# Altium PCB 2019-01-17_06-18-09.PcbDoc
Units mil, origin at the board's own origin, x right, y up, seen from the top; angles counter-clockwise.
Board outline 2440 x 2800 mil, 4 copper layers (Top Layer, MidLayer1, MidLayer2, Bottom Layer); 41 components, 20 nets, 113 pads, 111 vias.
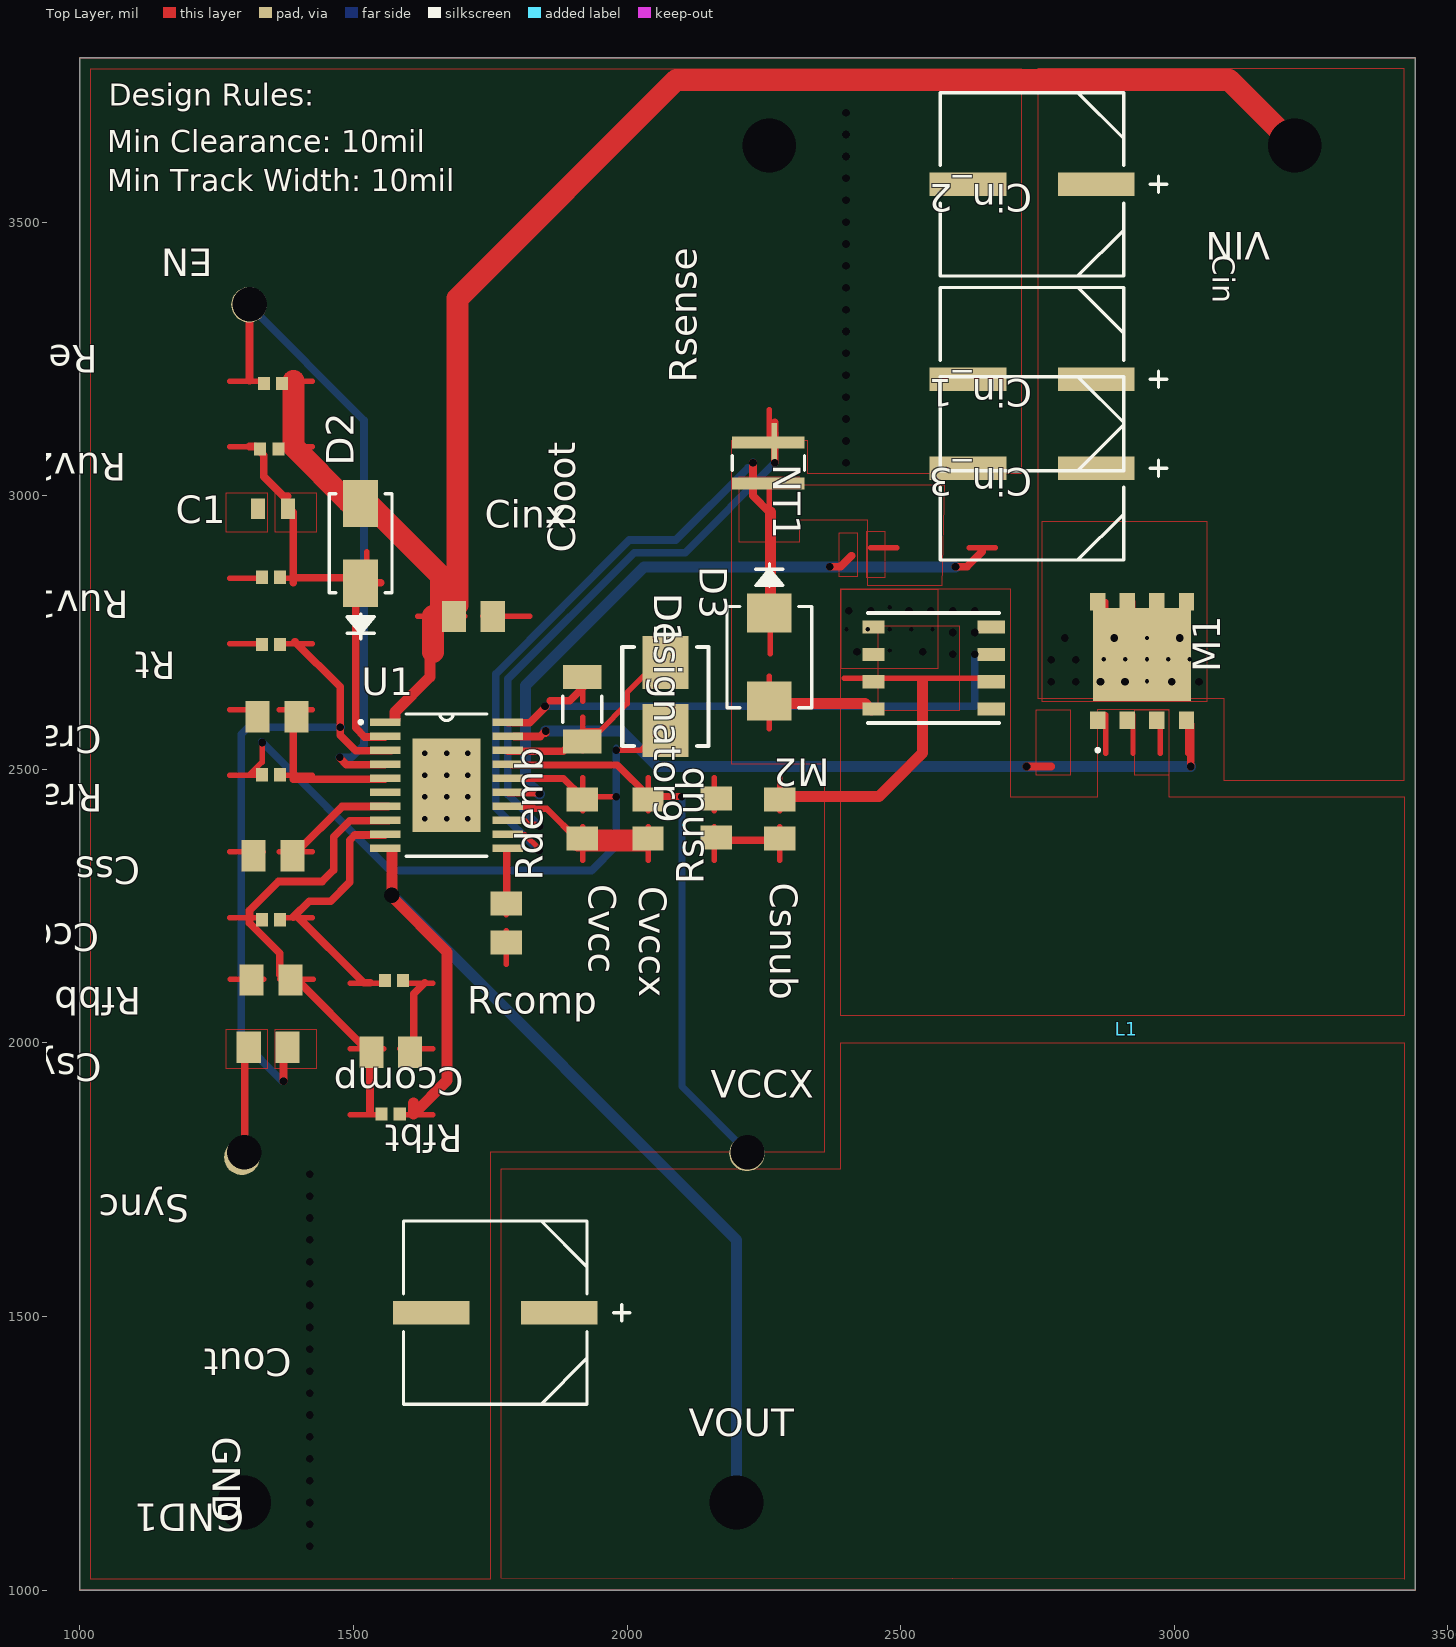
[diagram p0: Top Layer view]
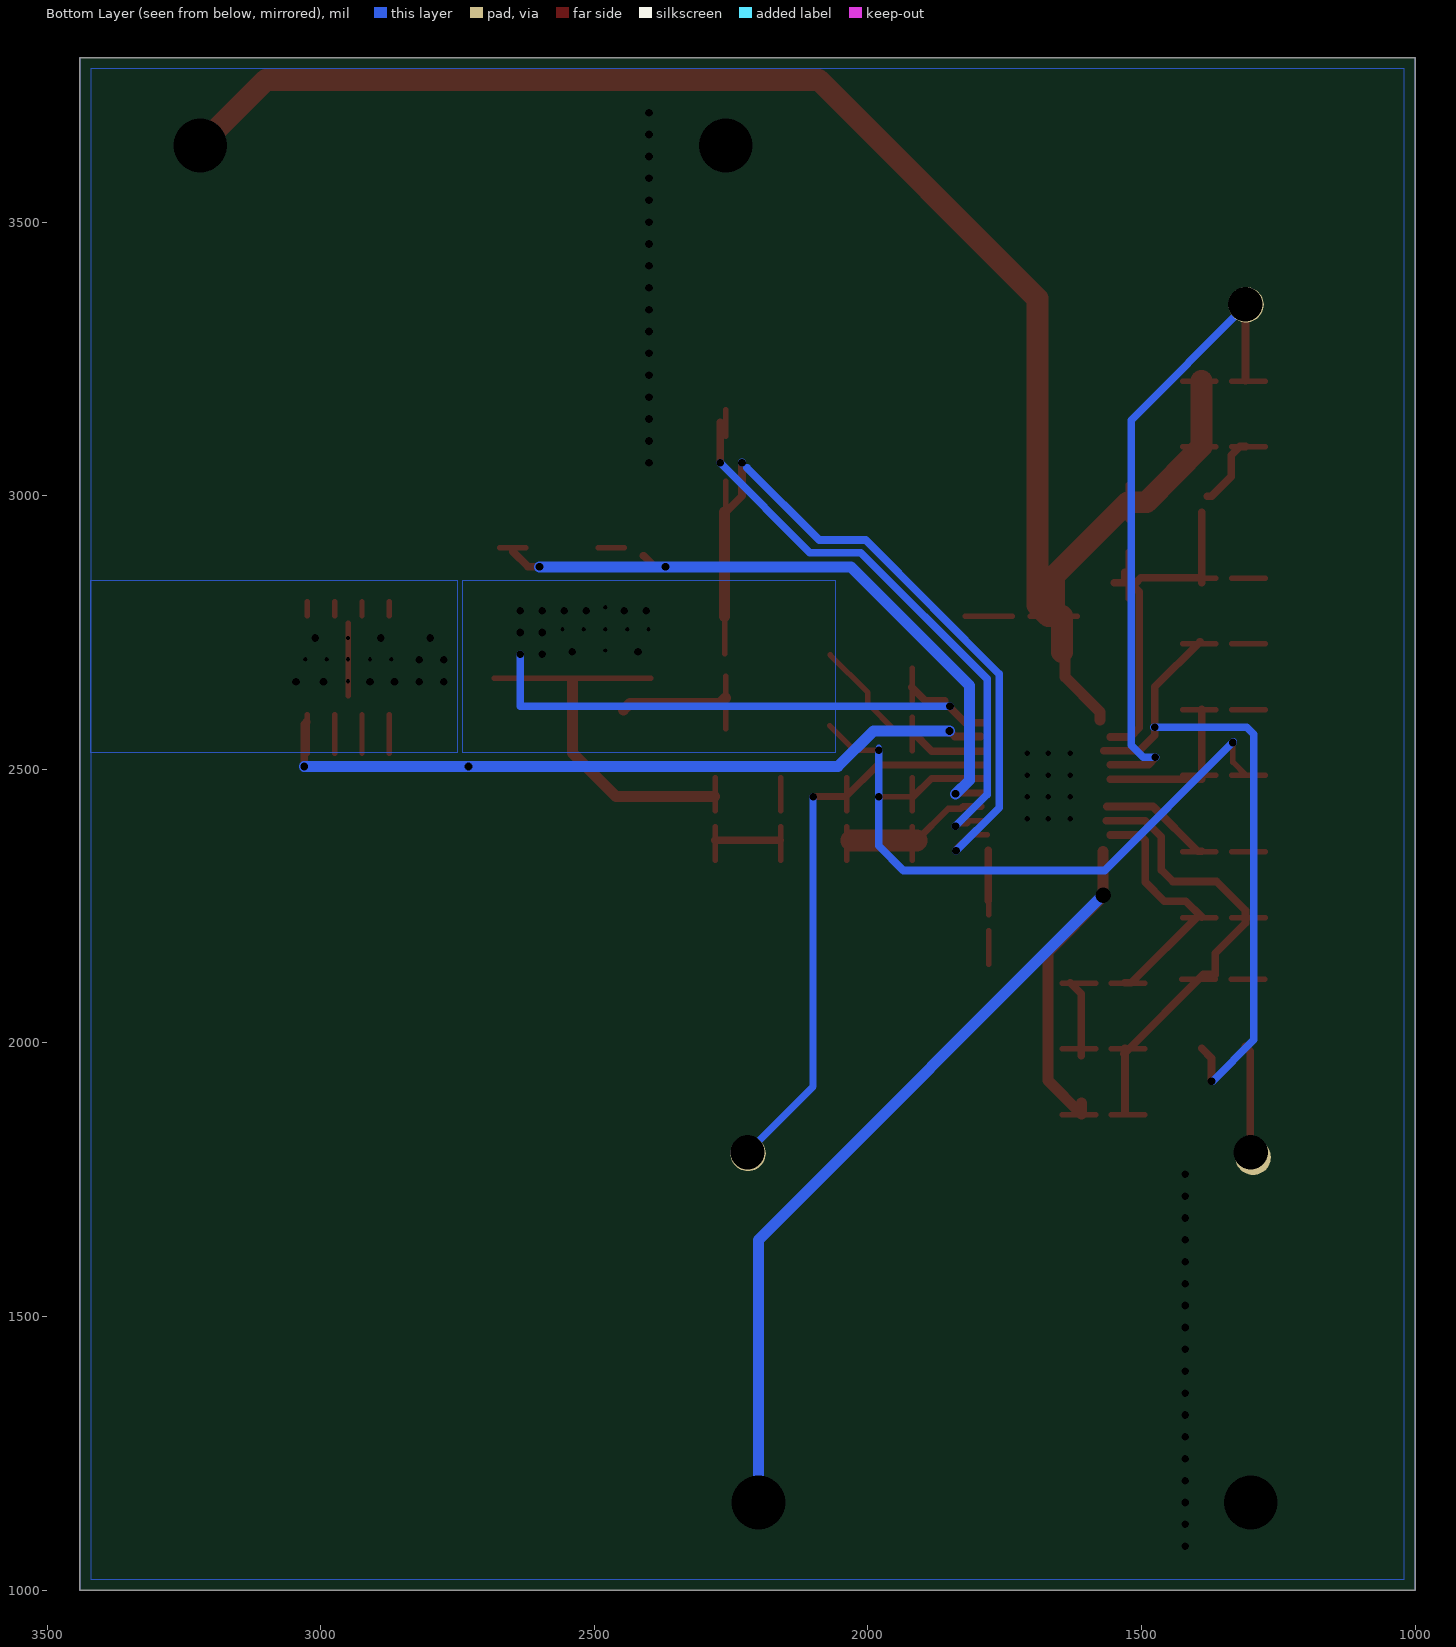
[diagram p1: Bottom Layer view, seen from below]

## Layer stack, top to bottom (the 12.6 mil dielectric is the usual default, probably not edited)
Top Layer: signal copper 1.4
Dielectric: core 12.6, FR-4, Dk 4.8
MidLayer1: signal copper 1.4
Dielectric: prepreg 12.6, FR-4, Dk 4.8
MidLayer2: signal copper 1.4
Dielectric: core 12.6, FR-4, Dk 4.8
Bottom Layer: signal copper 1.4

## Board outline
1000,1000 3440,1000 3440,3800 1000,3800

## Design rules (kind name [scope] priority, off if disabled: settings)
PlaneConnect [All] p0: scope1count=1 scope1_0_kind=Board scope1_0_value=Board scope2count=1 scope2_0_kind=Board scope2_0_value=Board commentlength=0 planeconnectstyle=Direct reliefexpansion=20 reliefentries=4 reliefconductorwidth=10 reliefairgap=10
PlaneConnect [All] p1: planeconnectstyle=Direct reliefexpansion=20 reliefentries=4 reliefconductorwidth=10 reliefairgap=10
PolygonConnect [All] p0: scope1count=1 scope1_0_kind=Board scope1_0_value=Board scope2count=1 scope2_0_kind=Board scope2_0_value=Board commentlength=0 connectstyle=Direct reliefconductorwidth=10 reliefentries=4 polygonreliefangle="90 Angle"
PolygonConnect [All] p1: connectstyle=Direct reliefconductorwidth=10 reliefentries=4 polygonreliefangle="90 Angle"

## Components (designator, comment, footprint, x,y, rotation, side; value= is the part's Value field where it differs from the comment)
C1 "" 0603 1353,2976 r0 top
Cboot "" 1206 1918,2610 r90 top
Ccomp "" 0805 1568,1983 r180 top
Ccomp2 "" 0402 1349,2225 r180 top
Cin_1 "" CAPSMT_62_E12 2740,3213 r180 top
Cin_2 "" CAPSMT_62_E12 2740,3569 r180 top
Cin_3 "" CAPSMT_62_E12 2740,3050 r180 top
Cinx "" 0805 1719,2779 r0 top
Cout "" CAPSMT_62_E12 1759,1507 r180 top
Cramp "" 0805 1360,2596 r180 top
Csnub "" 0805 2279,2409 r270 top
Css "" 0805 1353,2342 r180 top
Csync "" 0805 1344,1992 r180 top
Cvcc "" 0805 1918,2409 r270 top
Cvccx "" 0805 2038,2409 r270 top
D1 "" DO-214BA 2070,2633 r270 top
D2 "" SMA 1513,2913 r90 top
D3 "" SMB 2260,2705 r270 top
EN "" TP-1502 1309,3349 r180 top
GND "" TP-1502 2258,3638 r270 top
GND1 "" TP-1502 1300,1158 r180 top
L1 "" SER2918H 2913,2025 r270 top
M1 "" TRANS_NexFET_Q5A 2941,2698 r90 top
M2 "" PowerDFN56 2560,2685 r180 top
NT1 "" NET_TIED 2269,3099 r270 top
Rcomp "" 0402 1574,2114 r0 top
Rdemb "" 0805 1779,2219 r90 top
Renable "" 0402 1353,3205 r180 top
Rfbb "" 0805 1349,2115 r180 top
Rfbt "" 0402 1568,1870 r180 top
Rramp "" 0402 1349,2490 r180 top
Rsense "" 0612 2258,3060 r90 top
Rsnub "" 0805 2163,2411 r90 top
Rt "" 0402 1349,2728 r180 top
Ruv1 "" 0402 1349,2851 r180 top
Ruv2 "" 0402 1346,3085 r180 top
Sync "" TP-1502 1296,1791 r180 top
U1 "" MXA20A 1670,2471 r0 top
VCCX "" TP-1502 2219,1798 r0 top
VIN "" TP-1502 3219,3638 r180 top
VOUT "" TP-1502 2198,1159 r0 top

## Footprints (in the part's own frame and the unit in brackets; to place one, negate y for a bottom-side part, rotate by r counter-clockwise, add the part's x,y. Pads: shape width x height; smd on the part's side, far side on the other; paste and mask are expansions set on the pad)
0402 [mil]
  rect 22x24 smd: 1(-16.5,0) 2(16.5,0)
0603 [mil]
  rect 26x38 smd: 1(-27.5,0) 2(27.5,0)
0612 [mil]
  rect 22x132 smd: 1(-37.5,0) 2(37.5,0)
  silkscreen extent -13,-66 13,66
0805 [mil]
  rect 44x57 smd: 1(-35.5,0) 2(35.5,0)
1206 [mil]
  rect 44x71 smd: 1(-59,0) 2(59,0)
  silkscreen extent -24,-36 24,36
CAPSMT_62_E12 [mil]
  rect 140x43 smd: 1(-117,0) 2(117,0)
  silkscreen extent -246,-168 168,168
DO-214BA [mm]
  rect 2.45x2.15 smd: 1(-1.575,0) 2(1.575,0)
  silkscreen extent -2.3,-2 2.3,2
MXA20A [mil]
  rect 56x14 smd: 1(-112,115.16) 2(-112,89.57) 3(-112,63.98) 4(-112,38.39) 5(-112,12.8) 6(-112,-12.8) 7(-112,-38.39) 8(-112,-63.98) 9(-112,-89.57) 10(-112,-115.16) 11(112,-115.16) 12(112,-89.57) 13(112,-63.98) 14(112,-38.39) 15(112,-12.8) 16(112,12.8) 17(112,38.39) 18(112,63.98) 19(112,89.57) 20(112,115.16)
  rect 124x171 smd: 21(0,0)
  silkscreen extent -160,-130 74,130
NET_TIED [mil]
  rect 38x10 smd: 1(-15,0) 2(15,0)
PowerDFN56 [mm]
  rect 1.27x0.61 smd: 1(-2.67,1.905) 1(-2.67,1.905) 2(-2.67,0.635) 2(-2.67,0.635) 3(-2.67,-0.635) 3(-2.67,-0.635) 4(-2.67,-1.905) 4(-2.67,-1.905)
  rect 1.02x0.61 smd: 5(2.795,-1.905) 5(2.795,-1.905) 6(2.795,-0.635) 6(2.795,-0.635) 7(2.795,0.635) 7(2.795,0.635) 8(2.795,1.905) 8(2.795,1.905)
  silkscreen extent -3.05,-2.55 3.05,2.55
SER2918H [mil]
SMA [mil]
  rect 86x64 smd: 1(-73,0) 2(73,0)
  silkscreen extent -174,-58 90,58
SMB [mil]
  rect 71x81 smd: 1(-80.5,0) 2(80.5,0)
  silkscreen extent -171,-78 93,78
TP-1502 [mil]
  round 65 / inner round 0 / far side round 65 hole 32: 1(0,0)
TRANS_NexFET_Q5A [mm]
  rect 0.8x0.7 smd: 1(-2.752,2.055) 2(-2.752,0.685) 3(-2.752,-0.685) 4(-2.752,-2.055) 5(2.752,-2.055) 6(2.752,-0.685) 7(2.752,0.685) 8(2.752,2.055)
  rect 4.3x4.56 smd: 9(0.3,0)
  silkscreen extent -4.22,1.98 -4.07,2.13

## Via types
v1: diameter 0, hole 14, Top Layer to Bottom Layer, 76 vias
v2: diameter 0, hole 8, Top Layer to Bottom Layer, 14 vias
v3: diameter 0, hole 10, Top Layer to Bottom Layer, 12 vias
v4: diameter 0, hole 98, Top Layer to Bottom Layer, 4 vias
v5: diameter 0, hole 63, Top Layer to Bottom Layer, 3 vias
v6: diameter 0, hole 28, Top Layer to Bottom Layer, 2 vias

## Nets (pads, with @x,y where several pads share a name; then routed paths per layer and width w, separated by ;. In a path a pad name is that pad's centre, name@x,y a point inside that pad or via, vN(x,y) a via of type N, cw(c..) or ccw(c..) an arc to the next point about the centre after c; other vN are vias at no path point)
0: Cinx.2 Cout.2 Cramp.2 Css.2 Cvcc.2 Cvccx.2 NT1.1 NT1.2 Rdemb.2 Rfbb.2 Rsense.2 Rsnub.2 Rt.2 Ruv1.2 U1.6 U1.11 U1.13 U1.14 U1.21 | length 1218.4
  Top Layer w10: Rdemb.2@1779,2234 1779,2295 ; U1.13@1788,2406 1814,2406 1819,2400 1832,2400
  Top Layer w14: Rdemb.2@1780,2260 U1.11@1780,2352 ; v1(2270,3060) 2270,3134
  Bottom Layer w14: v1(1840,2396) 1782,2454 1782,2665 2013,2896 2106,2896 v1(2270,3060)
1: Cin_1.1 Cin_2.1 Cin_3.1 Cinx.1 D2.2 M1.5 M1.6 M1.7 M1.8 M1.9 Renable.1 Ruv2.1 U1.1 VIN.1 | length 3700.5
  Top Layer w10: Ruv2.1@1364,3089 1425,3089 ; Renable.1@1364,3209 1425,3209 ; D2.2@1524,2956 D2.2@1524,3020 ; 1617,2779.5 Cinx.1@1703,2779.5 ; M1.9@2874.5,2781 2874.5,2806 ; M1.9@2924.5,2781 M1.7@2924.5,2806 ; M1.9@2949.5,2634 M1.9@2949.5,2767 ; M1.9@2974.5,2781 M1.6@2974.5,2806 ; M1.9@3024.5,2781 M1.5@3024.5,2806
  Top Layer w20: 1391,3093 1393,3091 1393,3078 ; D2.2@1482,2988 1525,2988 D2.2@1530,2988 ; U1.1@1576,2590 1576,2605 1640,2669 1640,2709
  Top Layer w40: 1390,3210 1390,3090 1491,2988 1525,2988 1660,2853 1660,2780 ; 1645,2714 1645,2780 1670,2780 1690,2800 1690,3360 2090,3760 3100,3760 v4(3220,3640)
  other v1: 2775,2660 2820,2660 2865,2660 2910,2660 2995,2660 3045,2660 2775,2700 2820,2700 2800,2740 2890,2740 3010,2740
  other v2: 2950,2661 2871,2701 2910,2701 2950,2701 2989,2701 3028,2701 2950,2740
2: Css.1 U1.7 | length 268
  Top Layer w10: 1364,2349 1425,2349
  Top Layer w14: Css.1@1390,2350 1397,2350 1479,2432 U1.7@1563,2432
3: M2.4 U1.15 | length 1297.8
  Top Layer w10: 2625,2905 2673,2905
  Top Layer w13: U1.15@1782,2457 1837,2457
  Top Layer w14: v1(2370,2870) 2390,2870 2410,2890 ; v1(2600,2870) 2621,2870 2649,2898
  Bottom Layer w14: 1839,2455 v1(1840,2455)
  Bottom Layer w20: v1(1840,2455) 1814,2480 1814,2653 2031,2870 v1(2600,2870)
4: C1.2 D2.1 Ruv1.1 Ruv2.2 U1.2 | length 986.4
  Top Layer w10: 1274,3089 Ruv2.2@1335,3089 ; Ruv1.1@1364,2849 1425,2849 ; D2.1@1524,2812 1524,2898
  Top Layer w14: 1310,3090 1320,3090 1336,3074 1336,3035 1372,2999 1380,2999 ; 1390,2841 1390,2850 ; C1.2@1390,2970 1390,2850 ; D2.1@1530,2860 1530,2850 1504,2824 1504,2576 1520,2559 U1.2@1557,2559 ; 1550,2841 1510,2841 1501,2850 1390,2850
5: Csync.1 Rt.1 U1.3 | length 1288.9
  Top Layer w10: Rt.1@1364,2729 1425,2729
  Top Layer w14: v1(1372,1930) 1372,1972 Csync.1@1390,1990 ; 1393,2733 1476,2651 1476,2562 1504,2534 ; 1505,2534 U1.3@1569,2534
  Bottom Layer w14: 1295,2563 1295,2006 1370,1930 ; 1295,2564 1308,2577 1477,2577
  other v1: 1476,2577
6: Cramp.1 Rramp.2 U1.5 | length 417
  Top Layer w10: 1364,2489 1425,2489 ; 1364,2609 1425,2609
  Top Layer w14: Cramp.1@1390,2610 1390,2482 U1.5@1557,2482
7: EN.1 Renable.2 U1.4 | length 1227.4
  Top Layer w10: 1274,3209 Renable.2@1335,3209
  Top Layer w14: 1310,3210 EN.1@1310,3345 ; 1475,2521 1487,2508 U1.4@1557,2508
  Bottom Layer w14: EN.1@1310,3347 1519,3138 1519,2544 1497,2522 1474,2522
  other v1: 1475,2522
  other v5: 1310,3350
9: Ccomp2.1 Ccomp.1 U1.9 | length 583
  Top Layer w10: Ccomp2.1@1364,2229 1425,2229 ; 1494,2109 1555,2109
  Top Layer w14: 1390,2230 1419,2259 1458,2259 1493,2294 1493,2370 1502,2380 U1.9@1557,2380 ; 1394,2234 1519,2110 1530,2110
10: Ccomp2.2 Rcomp.2 Rfbb.1 Rfbt.2 U1.8 | length 1348.8
  Top Layer w10: 1274,2229 Ccomp2.2@1335,2229 ; Rfbb.1@1365,2116 1426,2116 ; 1494,1869 Rfbt.2@1555,1869 ; 1494,1989 1555,1989 ; 1584,1989 1645,1989 ; Rcomp.2@1584,2109 1645,2109
  Top Layer w14: 1530,1873 1530,1982 ; 1530,1990 1530,1982 ; 1532,1980 1530,1982 ; U1.8@1564,2406 1493,2406 1464,2377 1464,2316 1443,2295 1363,2295 1310,2242 1310,2230 1310,2219 1365,2164 1365,2125 1387,2125 1530,1982 ; 1610,1977 1610,1990 1610,2090 1630,2110
11: C1.1 Cin_1.2 Cin_2.2 Cin_3.2 Cout.1 Rfbt.1 U1.10 VOUT.1 | length 2954.7
  Top Layer w10: 1274,2349 1335,2349 ; 1274,2609 1335,2609 ; 1274,2729 1335,2729 ; 1274,2849 1335,2849 ; 1275,2116 1336,2116 ; Rfbt.1@1584,1869 1645,1869 ; 1736,2779.5 1822,2779.5 ; 1779,2144 1779,2205 ; 1919,2334 1919,2395 ; 2039,2334 2039,2395 ; 2159,2424 2159,2485 ; 2260,3109 2260,3157
  Top Layer w12: 1793,2432 1826,2432 1830,2428 1853,2428 1911,2370
  Top Layer w20: U1.10@1570,2350 v6(1570,2270) 1570,2267 1671,2166 1671,1931 1610,1870 1610,1890
  Top Layer w40: 1911,2370 2030,2370
  Bottom Layer w20: v6(1570,2270) 2200,1640 VOUT.1@2200,1150
  other v1: 1420,1080 1420,1120 1420,1160 1420,1200 1420,1240 1420,1280 1420,1320 1420,1360 1420,1400 1420,1440 1420,1480 1420,1520 1420,1560 1420,1600 1420,1640 1420,1680 1420,1720 1420,1760 2400,3060 2400,3100 2400,3140 2400,3180 2400,3220 2400,3260 2400,3300 2400,3340 2400,3380 2400,3420 2400,3460 2400,3500 2400,3540 2400,3580 2400,3620 2400,3660 2400,3700
  other v3: 1630,2410 1670,2410 1709,2410 1630,2450 1670,2450 1709,2450 1630,2489 1670,2489 1709,2489 1630,2529 1670,2529 1709,2529
  other v4: 1300,1160 2200,1160 2260,3640
  other v6: 2200,1160
13: D3.1 M2.1 M2.2 M2.3 Rsense.1 U1.12 | length 1628.7
  Top Layer w10: U1.12@1782,2380 1813,2380 1839,2355 v1(1839,2351) ; 2260,2920 Rsense.1@2260,3026 ; 2261.5,2711 2261.5,2847 ; 2445,2905 2493,2905
  Top Layer w14: v1(2230,3060) 2230,3000 2260,2970
  Top Layer w20: D3.1@2262,2779 2262,2970
  Bottom Layer w14: v1(1839,2351) 1760,2430 1760,2674 2004,2919 2089,2919 2221,3051 ; v1(2230,3060) 2230,3061
14: M1.4 U1.19 | length 1463.1
  Top Layer w10: 3024.5,2529 M1.4@3024.5,2600
  Top Layer w14: U1.19@1794,2560 1841,2560 v1(1851,2570) ; 1851,2566 1851,2568 ; v1(2730,2505) 2775,2505 ; M1.4@3026,2586 M1.4@3026,2587 ; v1(3030,2505) M1.4@3030,2582
  Bottom Layer w20: v1(1851,2570) 1990,2570 2055,2505 v1(2730,2505) v1(3030,2505)
15: Cboot.1 D1.1 GND1.1 GND.1 Rdemb.1 U1.18 | length 432.6
  Top Layer w10: Cboot.1@1919,2534 1919,2595 ; Cboot.1@1920,2570 1950,2570 2000,2620 2000,2640 D1.1@2069,2709
  Top Layer w14: U1.18@1782,2533 1883,2533 Cboot.1@1920,2570
16: Cvcc.1 D1.2 Rramp.1 U1.16 | length 1459.8
  Top Layer w10: 1274,2489 1335,2489 ; 1310,2490 1333,2513 v1(1333,2549) ; Cvcc.1@1917,2450 1920,2450 v1(1980,2450) ; Cvcc.1@1919,2424 1919,2485 ; 1985,2535 v1(1980,2535) 2025,2535 D1.2@2070,2580
  Top Layer w13: U1.16@1782,2483 1884,2483 Cvcc.1@1917,2450
  Bottom Layer w10: v1(1980,2535) 1980,2540
  Bottom Layer w14: 1332,2550 v1(1333,2549) 1567,2315 1935,2315 1980,2360 v1(1980,2450) v1(1980,2535)
17: Cboot.2 Csnub.1 D3.2 M1.1 M1.2 M1.3 M2.5 M2.6 M2.7 M2.8 U1.20 | length 2366.6
  Top Layer w10: 1919,2624 Cboot.2@1919,2685 ; 2259.5,2574 2259.5,2670 ; Csnub.1@2279,2424 2279,2485 ; 2397,2666 2683,2666 ; 2874.5,2529 2874.5,2600 ; 2924.5,2529 M1.2@2924.5,2600 ; 2974.5,2529 M1.3@2974.5,2600
  Top Layer w14: U1.20@1782,2585 1822,2585 1851,2614 ; 1860,2625 1895,2625 Cboot.2@1920,2650
  Top Layer w20: D3.2@2260,2630 2270,2620 2435,2620 M2.8@2447,2608 ; Csnub.1@2280,2450 2460,2450 2540,2530 2540,2659
  Bottom Layer w14: v1(1850,2615) 2635,2615 v1(2635,2710)
  other v1: 2595,2710 2420,2715 2540,2715 2595,2750 2635,2750 2405,2790 2445,2790 2515,2790 2555,2790 2595,2790 2635,2790
  other v2: 2480,2717 2401,2756 2440,2756 2480,2756 2519,2756 2558,2756 2480,2796
18: Ccomp.2 Rcomp.1
29: Csnub.2 Rsnub.1 | length 242
  Top Layer w10: 2159,2334 Rsnub.1@2159,2395 ; 2279,2334 Csnub.2@2279,2395
  Top Layer w14: Rsnub.1@2160,2370 Csnub.2@2280,2370
35: Cvccx.1 U1.17 VCCX.1 | length 1096.7
  Top Layer w10: Cvccx.1@2039,2424 2039,2485
  Top Layer w13: U1.17@1788,2508 1982,2508 2040,2450 v1(2100,2450)
  Bottom Layer w13: v1(2100,2450) 2100,1920 v5(2220,1800)
38: Csync.2 Sync.1 | length 197.7
  Top Layer w14: Sync.1@1301,1800 1301,1985 Csync.2@1310,1994
  other v5: 1300,1800

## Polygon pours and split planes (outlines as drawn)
38 on Top Layer " " (solid, pour order 0): 1267,1953 1267,2025 1342,2025 1342,1953
5 on Top Layer " " (solid, pour order 1): 1357,1953 1357,2025 1432,2025 1432,1953
4 on Top Layer " " (solid, pour order 2): 1357,2933 1357,3005 1432,3005 1432,2933
11 on Top Layer " " (solid, pour order 3): 1267,2933 1267,3005 1342,3005 1342,2933
1 on Top Layer " " (solid, pour order 4): 2759,2623 2759,2953 3059,2953 3059,2623
17 on Top Layer " " (solid, pour order 5): 2928,2489 2928,2609 2990,2609 2990,2489
14 on Top Layer " " (solid, pour order 6): 2748,2489 2748,2609 2810,2609 2810,2489
3 on Top Layer " " (solid, pour order 7): 2388,2852 2388,2932 2421,2932 2421,2852
13 on Top Layer " " (solid, pour order 8): 2438,2850 2438,2935 2471,2935 2471,2850
17 on Top Layer " " (solid, pour order 9): 2391,2684 2391,2829 2568,2829 2568,2684
11 on Top Layer " " (solid, pour order 16): 1770,1022 1770,1770 2390,1770 2390,2000 3400,2000 3420,2000 3420,1020
1 on Top Layer " " (solid, pour order 17): 2750,3780 2750,2630 3090,2630 3090,2480 3420,2480 3420,3780
11 on Top Layer " " (solid, pour order 18): 1020,3780 2720,3780 2720,3040 2330,3040 2330,3070 2330,3100 2190,3100 2190,2510 2360,2510 2360,1800 1750,1800 1750,1020 1020,1020
17 on Top Layer " " (solid, pour order 19): 2390,2830 2700,2830 2700,2450 2860,2450 2860,2610 2990,2610 2990,2450 3420,2450 3420,2050 2390,2050
13 on Top Layer " " (solid, pour order 20): 2205,3035 2315,3035 2315,3020 2580,3020 2575,2835 2440,2835 2440,2955 2315,2955 2315,2915 2205,2915
0 on Top Layer " " (solid, pour order 24): 2275,3106 2275,3094 2265,3094 2265,3106
0 on Top Layer " " (solid, pour order 25): 2265,3085 2265,3095 2275,3095 2275,3085
0 on Top Layer " " (solid, pour order 26): 2265,3105 2265,3115 2275,3115 2275,3105
11 on Bottom Layer " " (solid, pour order 21): 1020,1020 1020,3780 3420,3780 3420,1020
17 on Bottom Layer " " (solid, pour order 22): 2740,2845 2060,2845 2060,2530 2740,2530
1 on Bottom Layer " " (solid, pour order 23): 3420,2845 2750,2845 2750,2530 3420,2530
1 on MidLayer2 " " (solid, pour order 10): 3420,2845 2750,2845 2750,2530 3420,2530
17 on MidLayer2 " " (solid, pour order 11): 2740,2845 2060,2845 2060,2530 2740,2530
1 on MidLayer2 " " (solid, pour order 12): 1020,1020 3420,1020 3420,3780 1020,3780
1 on MidLayer1 " " (solid, pour order 13): 3420,2845 2750,2845 2750,2530 3420,2530
17 on MidLayer1 " " (solid, pour order 14): 2740,2530 2740,2845 2060,2845 2060,2530
11 on MidLayer1 " " (solid, pour order 15): 1020,1020 3420,1020 3420,3780 1020,3780
no net on Top Solder "Top Layer-No Net" (solid, remove dead copper): 2846.31,2790.62 2873.87,2790.62 2873.87,2822.11 2846.31,2822.11
no net on Top Solder "Top Layer-No Net" (solid, remove dead copper): 2851.24,2790.52 2851.24,2621.23 3030.76,2621.23 3030.76,2790.52
no net on Top Layer "Top Layer-No Net" (solid, remove dead copper): 2608.08,2761.64 2458.08,2761.64 2458.08,2607.7 2608.08,2607.7
no net on Top Solder "Top Layer-No Net" (solid, remove dead copper): 2610.08,2763.64 2456.08,2763.64 2456.08,2605.7 2610.08,2605.7
no net on Top Paste "Top Layer-No Net" (solid, remove dead copper): 2608.08,2761.64 2458.08,2761.64 2458.08,2607.7 2608.08,2607.7
no net on Top Overlay "Top Layer-No Net" (solid, remove dead copper): 2683.03,2584.61 2667.28,2584.61 2667.28,2574.76 2683.03,2574.76

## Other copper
Multi-Layer:
  the board outline again, w1

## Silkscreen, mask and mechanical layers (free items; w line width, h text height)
Top Overlay:
  text "Design Rules:" at 1053,3713 h40
  text "Min Clearance: 10mil" at 1050,3628 h40
  text "Min Track Width: 10mil" at 1050,3556 h40
  text "Cin" at 3070,3440 h40 r270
